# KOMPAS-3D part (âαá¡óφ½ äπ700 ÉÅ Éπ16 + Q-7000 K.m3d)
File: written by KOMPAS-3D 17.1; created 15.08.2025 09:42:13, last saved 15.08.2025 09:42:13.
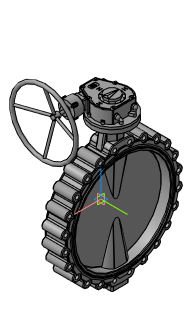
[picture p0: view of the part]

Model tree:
1. Операция без истории:1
